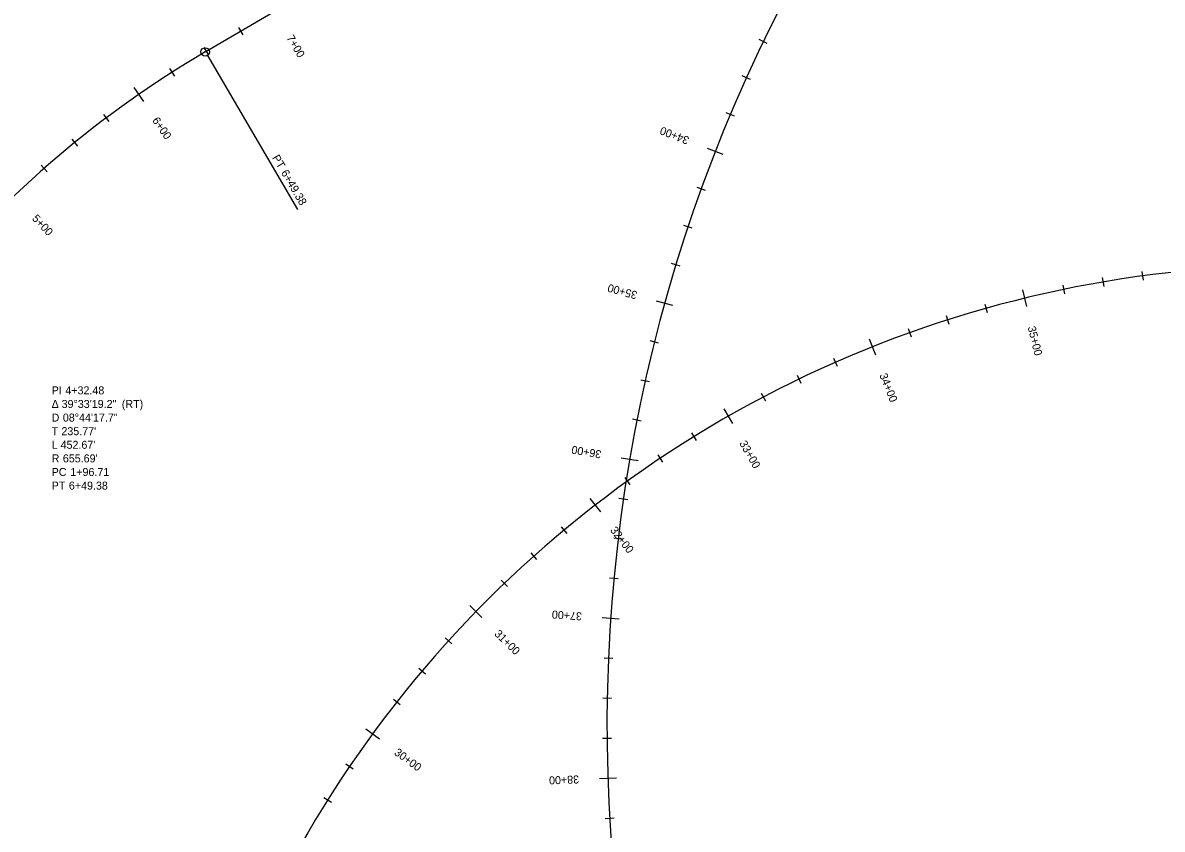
# Model space of a CAD drawing. Extents: x 2300830 to 2307917, y 756066 to 766359.
# Drawn here: x 2302821 to 2303533, y 761628 to 762132 of the extents above; entities that cross this region are included whole.
import ezdxf

# ---------------------------------------------------------------- set-up
doc = ezdxf.new("R2010")
doc.units = 0
for name, color, linetype in [('Default', 7, 'Continuous'), ('Draft_Curve Data Label', 7, 'Continuous'), ('Draft_Station Cardinal Lines', 7, 'Continuous'), ('Draft_Station Cardinal Points', 7, 'Continuous'), ('Draft_Station Labels Major', 7, 'Continuous'), ('Draft_Station Ticks Major', 7, 'Continuous'), ('Draft_Station Ticks Minor', 7, 'Continuous'), ('Geom_Baseline', 7, 'Continuous')]:
    doc.layers.add(name, color=color, linetype=linetype)

msp = doc.modelspace()

# ---------------------------------------------------------------- linework, layer by layer
at = {"layer": 'Default'}
msp.add_line((2302935.16, 762113.72), (2303299.17, 762327.41), dxfattribs=at)
for centre, radius, start, end in [((2304169.7, 761693.02), 983.53, 137.61666, 272.52241), ((2303267.11, 761548.26), 655.69, 120.41478, 159.97011), ((2303616.31, 761265.54), 714.7, 64.28167, 164.6807)]:
    msp.add_arc(centre, radius, start, end, dxfattribs=at)
at = {"layer": 'Draft_Station Cardinal Lines'}
msp.add_line((2302936.52, 762111.42), (2302992.88, 762015.41), dxfattribs=at)
at = {"layer": 'Draft_Station Cardinal Points'}
for p, q in [((2302935.16, 762113.72), (2302935.16, 762113.72)), ((2302992.88, 762015.41), (2302992.88, 762015.41))]:
    msp.add_line(p, q, dxfattribs=at)
msp.add_circle((2302935.16, 762113.72), 2.67, dxfattribs=at)
at = {"layer": 'Draft_Station Ticks Major'}
for p, q in [((2302890.52, 762091.53), (2302896.57, 762082.8)), ((2303258.8, 762049.57), (2303248.91, 762053.44)), ((2303445.86, 761965.11), (2303448.37, 761954.79)), ((2303227.31, 761955.28), (2303217.08, 761958.12)), ((2303349.96, 761934.51), (2303353.89, 761924.64)), ((2303259.27, 761890.82), (2303264.53, 761881.6)), ((2303205.56, 761858.27), (2303195.1, 761860.06)), ((2303175.55, 761834.92), (2303182.05, 761826.52)), ((2303100.45, 761767.89), (2303108.06, 761760.48)), ((2303193.77, 761759.56), (2303183.17, 761760.28)), ((2303035.43, 761691.03), (2303044, 761684.76)), ((2303192.06, 761660.16), (2303181.44, 761659.8))]:
    msp.add_line(p, q, dxfattribs=at)
at = {"layer": 'Draft_Station Ticks Minor'}
for p, q in [((2302955.86, 762129.07), (2302958.66, 762124.31)), ((2302934.3, 762116.41), (2302937.1, 762111.65)), ((2303286.29, 762119.05), (2303281.31, 762121.45)), ((2302912.89, 762103.32), (2302915.86, 762098.66)), ((2303275.74, 762096.46), (2303270.71, 762098.73)), ((2302871.64, 762074.72), (2302874.95, 762070.3)), ((2303265.78, 762073.61), (2303260.69, 762075.75)), ((2302851.86, 762059.26), (2302855.34, 762054.98)), ((2302832.68, 762043.06), (2302836.32, 762038.91)), ((2303247.61, 762027.18), (2303242.42, 762029.07)), ((2303239.41, 762003.64), (2303234.18, 762005.39)), ((2303231.82, 761979.9), (2303226.54, 761981.51)), ((2303520.42, 761976.56), (2303521.16, 761971.09)), ((2303470.95, 761968.12), (2303472.07, 761962.71)), ((2303495.61, 761972.77), (2303496.54, 761967.33)), ((2303422.2, 761956.24), (2303423.69, 761950.93)), ((2303398.16, 761949.03), (2303399.84, 761943.77)), ((2303374.39, 761940.98), (2303376.25, 761935.79)), ((2303218.45, 761931.87), (2303213.1, 761933.21)), ((2303327.77, 761922.42), (2303329.99, 761917.37)), ((2303304.97, 761911.93), (2303307.36, 761906.95)), ((2303212.69, 761907.61), (2303207.3, 761908.82)), ((2303282.55, 761900.64), (2303285.12, 761895.76)), ((2303207.54, 761883.22), (2303202.13, 761884.29)), ((2303238.98, 761875.76), (2303241.88, 761871.06)), ((2303217.86, 761862.19), (2303220.93, 761857.6)), ((2303197.24, 761847.89), (2303200.47, 761843.41)), ((2303199.12, 761834.08), (2303193.66, 761834.88)), ((2303157.56, 761817.17), (2303161.09, 761812.93)), ((2303195.85, 761809.37), (2303190.37, 761810.03)), ((2303138.55, 761800.79), (2303142.22, 761796.67)), ((2303120.12, 761783.76), (2303123.94, 761779.77)), ((2303193.21, 761784.58), (2303187.71, 761785.1)), ((2303085.11, 761747.8), (2303089.2, 761744.09)), ((2303189.82, 761734.84), (2303184.3, 761735.08)), ((2303068.57, 761728.93), (2303072.78, 761725.37)), ((2303052.7, 761709.49), (2303057.03, 761706.08)), ((2303189.07, 761709.92), (2303183.55, 761710.02)), ((2303188.96, 761685), (2303183.44, 761684.95)), ((2303023.04, 761669.01), (2303027.61, 761665.9)), ((2303009.3, 761648.01), (2303013.97, 761645.07)), ((2303190.63, 761635.17), (2303185.12, 761634.84))]:
    msp.add_line(p, q, dxfattribs=at)
at = {"layer": 'Geom_Baseline'}
msp.add_line((2302935.16, 762113.72), (2303299.17, 762327.41), dxfattribs=at)
for centre, radius, start, end in [((2304169.7, 761693.02), 983.53, 137.61666, 272.52241), ((2303267.11, 761548.26), 655.69, 120.41478, 159.97011), ((2303616.31, 761265.54), 714.7, 64.28167, 164.6807)]:
    msp.add_arc(centre, radius, start, end, dxfattribs=at)

# ---------------------------------------------------------------- texts
at = {"layer": 'Draft_Curve Data Label'}
for s, p in [('PI ', (2302839.21, 761899.87)), ('4+32.48', (2302847.75, 761899.87)), ('Δ ', (2302839.21, 761891.37)), ('39°33\'19.2"', (2302845.43, 761891.37)), (' (RT)', (2302881.17, 761891.37)), ('D ', (2302839.21, 761882.87)), ('08°44\'17.7"', (2302846.2, 761882.87)), ('T ', (2302839.21, 761874.37)), ("235.77'", (2302845.3, 761874.37)), ('L ', (2302839.21, 761865.87)), ("452.67'", (2302844.78, 761865.87)), ('R ', (2302839.21, 761857.37)), ("655.69'", (2302846.2, 761857.37)), ('PC ', (2302839.21, 761848.87)), ('1+96.71', (2302850.86, 761848.87)), ('PT ', (2302839.21, 761840.37)), ('6+49.38', (2302849.96, 761840.37))]:
    msp.add_text(s, height=5, dxfattribs=at).set_placement(p)
at = {"layer": 'Draft_Station Cardinal Points'}
for s, p in [('PT', (2302976.8, 762047.7)), ('6+49.38', (2302982.3, 762038.33))]:
    msp.add_text(s, height=5, rotation=300.41478, dxfattribs=at).set_placement(p)
at = {"layer": 'Draft_Station Labels Major'}
for s, rotation, p in [('7+00', 300.41478, (2302985.78, 762122.56)), ('6+00', 304.72935, (2302901.76, 762070.92)), ('34+00', 158.62315, (2303237.98, 762060.41)), ('5+00', 313.4676, (2302826.6, 762009.35)), ('35+00', 164.44864, (2303205.5, 761963.94)), ('35+00', 283.6928, (2303448.96, 761941.84)), ('34+00', 291.70954, (2303356.27, 761911.9)), ('36+00', 170.27414, (2303182.98, 761864.68)), ('33+00', 299.72628, (2303268.67, 761869.31)), ('32+00', 307.74303, (2303187.86, 761814.93)), ('37+00', 176.09964, (2303170.65, 761763.64)), ('31+00', 315.75977, (2303115.43, 761749.81)), ('30+00', 323.77651, (2303052.79, 761675.23)), ('38+00', 181.92514, (2303168.64, 761661.87))]:
    msp.add_text(s, height=5, rotation=rotation, dxfattribs=at).set_placement(p)

doc.saveas('drawing.dxf')
